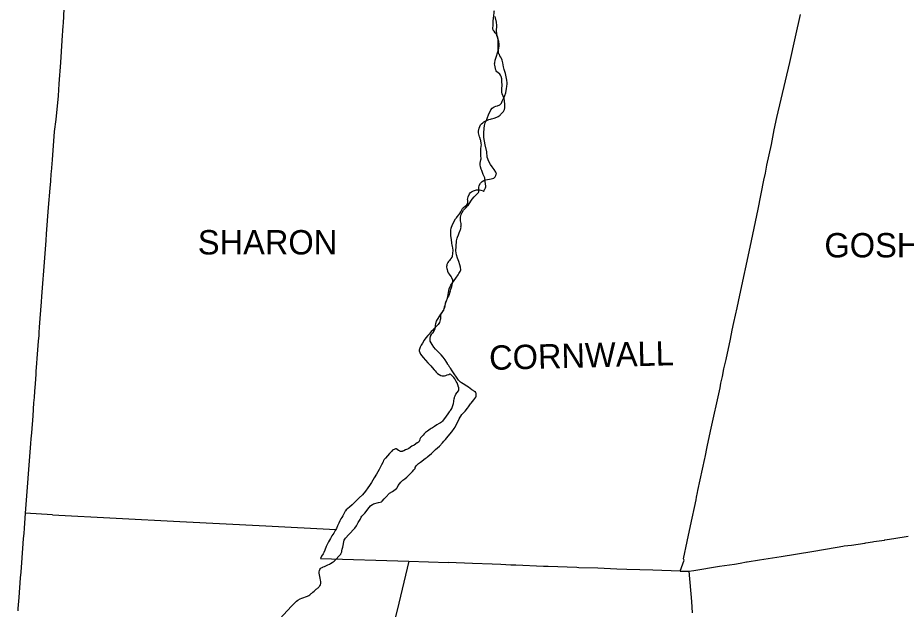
# Model space of a CAD drawing. Extents: x 0 to 2603, y -226 to 830.
# Drawn here: x 58.42 to 107.65, y 640.75 to 673.53 of the extents above; entities that cross this region are included whole.
import ezdxf

# ---------------------------------------------------------------- set-up
doc = ezdxf.new("R2010")
doc.units = 0
for name, color, linetype in [('CT_TSH_Map_Town_Limits', 7, 'Continuous'), ('CT_TSH_Map_Town_Text', 7, 'Continuous'), ('CT_TSH_Map_US_and_State_Routes', 7, 'Continuous')]:
    doc.layers.add(name, color=color, linetype=linetype)

msp = doc.modelspace()

# ---------------------------------------------------------------- linework, layer by layer
at = {"layer": 'CT_TSH_Map_Town_Limits'}
for points in [[(61.031, 675.236), (60.931, 673.222), (60.919, 673.075), (60.872, 672.278), (60.785, 671.041), (60.705, 669.873), (60.659, 669.204), (60.531, 667.883), (60.444, 667.228), (60.323, 665.65), (60.273, 664.984), (60.26, 664.878), (60.234, 664.477), (60.199, 664.083), (60.116, 663.02), (60.001, 661.559), (59.983, 661.187), (59.902, 660.217), (59.743, 658.078), (59.723, 657.778), (59.65, 656.871), (59.618, 656.382), (59.59, 656.089), (59.582, 655.911), (59.553, 655.613), (59.484, 654.647), (59.47, 654.38), (59.432, 653.916), (59.426, 653.757), (59.397, 653.509), (59.382, 653.246), (59.352, 652.835), (59.33, 652.478), (59.301, 652.195), (59.255, 651.46), (59.176, 650.527), (59.153, 650.196), (59.129, 649.932), (58.837, 646.072)], [(85.403, 668.545), (85.402, 668.697), (85.393, 668.942), (85.364, 669.049), (85.271, 669.317), (85.248, 669.411), (85.242, 669.486), (85.248, 669.583), (85.254, 669.79), (85.251, 670.005), (85.235, 670.148), (85.204, 670.276), (85.167, 670.355), (85.131, 670.4), (85.017, 670.499), (84.966, 670.538), (84.926, 670.588), (84.916, 670.618), (84.848, 670.904), (84.846, 670.97), (84.851, 671.033), (84.882, 671.179), (84.93, 671.337), (85.027, 671.636), (85.081, 671.839), (85.099, 671.972), (85.089, 672.094), (85.072, 672.184), (85.071, 672.212), (85.044, 672.318), (84.986, 672.528), (84.952, 672.783), (84.967, 673.091), (84.941, 673.29), (84.88, 673.593)], [(95.121, 642.851), (95.342, 643.466), (95.314, 643.536), (95.51, 644.512), (95.692, 645.37), (96.004, 646.816), (96.032, 646.954), (96.09, 647.22), (96.112, 647.327), (96.492, 649.109), (96.504, 649.174), (96.626, 649.752), (96.813, 650.615), (97.336, 653.016), (97.386, 653.287), (97.467, 653.654), (97.553, 654.065), (97.668, 654.59), (97.913, 655.716), (98.01, 656.213), (98.104, 656.639), (98.28, 657.458), (98.425, 658.157), (99, 660.816), (99.442, 662.918), (99.769, 664.522), (99.844, 664.916), (99.934, 665.357), (100.177, 666.51), (100.335, 667.321), (100.477, 668.008), (101.195, 671.043), (101.524, 672.472), (101.79, 673.71)], [(82.387, 660.139), (82.432, 660.184), (82.486, 660.263), (82.507, 660.312), (82.533, 660.465), (82.543, 660.652), (82.533, 660.765), (82.512, 660.872), (82.499, 660.91), (82.48, 661.054), (82.471, 661.08), (82.431, 661.353), (82.423, 661.451), (82.416, 661.51), (82.418, 661.536), (82.423, 661.759), (82.439, 661.872), (82.449, 661.924), (82.486, 662.019), (82.601, 662.247), (82.685, 662.383), (82.73, 662.445), (82.775, 662.497), (82.861, 662.606), (82.919, 662.676), (82.971, 662.774), (83.058, 662.954), (83.102, 663.001), (83.225, 663.107), (83.28, 663.141), (83.306, 663.162), (83.34, 663.209), (83.357, 663.259), (83.361, 663.305), (83.357, 663.413), (83.347, 663.458), (83.354, 663.53), (83.373, 663.603), (83.449, 663.776), (83.506, 663.842), (83.572, 663.889), (83.634, 663.922), (83.672, 663.94), (83.837, 663.988), (83.926, 663.998), (83.999, 663.988), (84.075, 663.971), (84.203, 663.929), (84.236, 663.918), (84.247, 663.919), (84.264, 663.944), (84.292, 664.002), (84.302, 664.035), (84.333, 664.102), (84.352, 664.154), (84.357, 664.197), (84.32, 664.446), (84.316, 664.525), (84.304, 664.596), (84.297, 664.662), (84.253, 664.769), (84.215, 664.851), (84.135, 665.069), (84.102, 665.141), (84.062, 665.271), (84.039, 665.387), (84.04, 665.462), (84.082, 665.656), (84.092, 665.714), (84.089, 665.9), (84.087, 666.269), (84.103, 666.407), (84.111, 666.478), (84.104, 666.569), (84.083, 666.719), (84.071, 666.768), (84.02, 666.887), (84.011, 666.933), (83.968, 667.081), (83.957, 667.156), (83.958, 667.24), (83.994, 667.402), (84.025, 667.494), (84.071, 667.598), (84.115, 667.658), (84.184, 667.715), (84.25, 667.759), (84.319, 667.792), (84.443, 667.853), (84.516, 667.887), (84.615, 667.915), (84.668, 667.934), (84.818, 667.973), (84.967, 668.019), (85.036, 668.048), (85.15, 668.139), (85.174, 668.163), (85.334, 668.34), (85.381, 668.413), (85.392, 668.442), (85.403, 668.545)], [(82.387, 660.139), (82.345, 660.069), (82.294, 660.014), (82.257, 659.958), (82.224, 659.893), (82.202, 659.847), (82.189, 659.797), (82.181, 659.751), (82.187, 659.7), (82.192, 659.642), (82.206, 659.573), (82.239, 659.492), (82.278, 659.393), (82.325, 659.322), (82.364, 659.272), (82.382, 659.262)], [(82.374, 658.356), (82.403, 658.426), (82.474, 658.642), (82.531, 658.889), (82.528, 658.978), (82.472, 659.107), (82.437, 659.19), (82.403, 659.242), (82.382, 659.262)], [(82.374, 658.356), (82.349, 658.262), (82.322, 658.192), (82.285, 658.105), (82.242, 658.02), (82.193, 657.908), (82.143, 657.798), (82.106, 657.693), (82.081, 657.584), (82.056, 657.491), (82.028, 657.39), (82.004, 657.323), (81.956, 657.255), (81.887, 657.143), (81.862, 657.075), (81.849, 657.049), (81.849, 656.983), (81.837, 656.851), (81.82, 656.781), (81.802, 656.712), (81.782, 656.639), (81.753, 656.576), (81.717, 656.531), (81.635, 656.449), (81.55, 656.366), (81.499, 656.303), (81.417, 656.213), (81.332, 656.134), (81.213, 655.991), (81.145, 655.923), (81.026, 655.782), (80.938, 655.661), (80.84, 655.503), (80.767, 655.375), (80.723, 655.271), (80.673, 655.164), (80.668, 655.108), (80.671, 655.061), (80.692, 654.973), (80.734, 654.888), (80.876, 654.7), (81.147, 654.406), (81.31, 654.236), (81.385, 654.154), (81.5, 654.016), (81.554, 653.953), (81.612, 653.884), (81.683, 653.82), (81.768, 653.763), (81.87, 653.711), (81.93, 653.691), (81.987, 653.68), (82.063, 653.681), (82.137, 653.706), (82.209, 653.733), (82.282, 653.758), (82.318, 653.755), (82.342, 653.774)], [(82.326, 651.687), (82.405, 651.762), (82.469, 651.882), (82.513, 651.99), (82.557, 652.148), (82.581, 652.271), (82.581, 652.301), (82.606, 652.409), (82.624, 652.469), (82.63, 652.501), (82.652, 652.573), (82.704, 652.672), (82.763, 652.756), (82.845, 652.845), (82.862, 652.89), (82.863, 652.96), (82.859, 653.012), (82.831, 653.109), (82.828, 653.127), (82.787, 653.246), (82.761, 653.3), (82.718, 653.377), (82.64, 653.51), (82.58, 653.593), (82.493, 653.69), (82.424, 653.754), (82.374, 653.774), (82.342, 653.774)], [(82.326, 651.687), (82.243, 651.575), (82.156, 651.454), (82.068, 651.315), (81.989, 651.219), (81.954, 651.17), (81.931, 651.145), (81.911, 651.123), (81.897, 651.112), (81.846, 651.08), (81.763, 651.035), (81.649, 650.963), (81.515, 650.881), (81.404, 650.809), (81.321, 650.759), (81.268, 650.73), (81.204, 650.681), (81.118, 650.614), (81.021, 650.54), (80.933, 650.461), (80.877, 650.4), (80.825, 650.343), (80.765, 650.273), (80.745, 650.252), (80.705, 650.174), (80.684, 650.107), (80.655, 650.051), (80.621, 650.016), (80.606, 650.005), (80.575, 649.978), (80.554, 649.966), (80.388, 649.848), (80.264, 649.78), (80.086, 649.666), (80.016, 649.623), (79.915, 649.579), (79.805, 649.529), (79.758, 649.508), (79.738, 649.507), (79.713, 649.498), (79.673, 649.491), (79.65, 649.491), (79.629, 649.495), (79.6, 649.505), (79.568, 649.52), (79.512, 649.55), (79.453, 649.609), (79.438, 649.621), (79.424, 649.629), (79.402, 649.634), (79.383, 649.637), (79.356, 649.634), (79.322, 649.624), (79.272, 649.605), (79.221, 649.576), (79.19, 649.556), (79.142, 649.513), (79.011, 649.379), (78.792, 649.13), (78.731, 649.055), (78.697, 649.007), (78.683, 648.99), (78.66, 648.927), (78.57, 648.745), (78.442, 648.501), (78.291, 648.239), (78.167, 648.029), (78.026, 647.768), (77.92, 647.605), (77.824, 647.484), (77.682, 647.297), (77.517, 647.09), (77.341, 646.916), (77.145, 646.715), (76.949, 646.53), (76.805, 646.41), (76.712, 646.324), (76.628, 646.254), (76.587, 646.206), (76.562, 646.175), (76.503, 646.078), (76.433, 645.928), (76.375, 645.831), (76.332, 645.75), (76.272, 645.655), (76.208, 645.511), (76.136, 645.367), (76.075, 645.225), (76.042, 645.173)], [(58.837, 646.072), (58.769, 645.234), (58.756, 644.943), (58.728, 644.665), (58.711, 644.39), (58.589, 642.806), (58.559, 642.488), (58.477, 641.393), (58.436, 640.783), (58.423, 640.667)], [(60.341, 645.972), (58.837, 646.072)], [(60.341, 645.972), (67.41, 645.603), (72.165, 645.364), (76.042, 645.173)], [(76.042, 645.173), (76.005, 645.117), (75.93, 644.97), (75.833, 644.82), (75.746, 644.668), (75.641, 644.484), (75.567, 644.337), (75.513, 644.226), (75.431, 644.026), (75.38, 643.893), (75.352, 643.816), (75.258, 643.681), (75.193, 643.555), (80.1, 643.411)], [(95.609, 642.852), (95.882, 642.894), (97.308, 643.128), (98.127, 643.255), (98.457, 643.31), (98.793, 643.367), (98.846, 643.373), (99.523, 643.488), (100.712, 643.675), (102.416, 643.953), (103.83, 644.191), (104.146, 644.238), (104.22, 644.254), (104.611, 644.307), (105.36, 644.411), (105.409, 644.427), (105.785, 644.479), (105.859, 644.496), (106.447, 644.585), (106.467, 644.593), (106.726, 644.625), (107.53, 644.765), (107.764, 644.793)], [(80.1, 643.411), (79.534, 641.088), (78.955, 638.71), (77.491, 637.157), (77.606, 636.187)], [(80.1, 643.411), (82.266, 643.331)], [(95.121, 642.851), (93.603, 642.911), (92.167, 642.96), (91.611, 642.977), (90.56, 643.019), (89.515, 643.051), (89.391, 643.06), (87.807, 643.12), (87.556, 643.124), (86.019, 643.188), (85.738, 643.197), (85.183, 643.223), (84.71, 643.238), (83.611, 643.28), (82.266, 643.331)], [(95.121, 642.851), (95.609, 642.852)], [(95.609, 642.852), (95.751, 641.169), (95.796, 640.551)]]:
    msp.add_lwpolyline(points, dxfattribs=at)
at = {"layer": 'CT_TSH_Map_US_and_State_Routes'}
for points in [[(84.759, 673.118), (84.759, 673.199), (84.763, 673.334), (84.775, 673.513), (84.81, 673.794), (84.826, 673.878), (84.837, 673.94)], [(84.877, 672.696), (84.819, 672.778), (84.772, 672.847), (84.753, 672.926), (84.759, 673.118)], [(84.976, 672.548), (84.943, 672.616), (84.877, 672.696)], [(85.014, 672.449), (84.976, 672.548)], [(85.044, 671.877), (85.032, 672.261), (85.032, 672.343), (85.014, 672.449)], [(85.055, 671.604), (85.044, 671.877)], [(85.219, 671.273), (85.18, 671.35), (85.142, 671.416), (85.107, 671.486), (85.081, 671.525), (85.055, 671.604)], [(85.256, 671.184), (85.219, 671.273)], [(85.408, 669.221), (85.457, 669.372), (85.489, 669.496), (85.503, 669.596), (85.526, 669.733), (85.537, 669.856), (85.537, 669.92), (85.517, 670.075), (85.488, 670.255), (85.438, 670.435), (85.381, 670.667), (85.357, 670.735), (85.335, 670.818), (85.304, 671.024), (85.256, 671.184)], [(84.702, 665.267), (84.608, 665.397), (84.517, 665.564), (84.437, 665.798), (84.415, 666.098), (84.317, 666.493), (84.239, 666.897), (84.246, 667.145), (84.27, 667.39), (84.29, 667.56), (84.325, 667.705), (84.406, 667.89), (84.446, 668), (84.501, 668.156), (84.637, 668.427), (84.715, 668.525), (84.813, 668.586), (84.914, 668.627), (85.013, 668.653), (85.134, 668.708), (85.218, 668.803), (85.267, 668.898), (85.339, 669.047), (85.374, 669.126), (85.386, 669.159)], [(85.386, 669.159), (85.408, 669.221)], [(84.811, 665.125), (84.702, 665.267)], [(84.918, 664.969), (84.811, 665.125)], [(83.972, 663.918), (83.963, 664.057), (83.97, 664.128), (83.996, 664.229), (84.063, 664.358), (84.158, 664.455), (84.245, 664.509), (84.326, 664.542), (84.442, 664.567), (84.556, 664.579), (84.662, 664.596), (84.794, 664.644), (84.875, 664.71), (84.917, 664.781), (84.935, 664.856), (84.94, 664.88), (84.917, 664.969)], [(83.126, 662.862), (83.262, 663.016), (83.337, 663.098), (83.376, 663.131), (83.524, 663.364), (83.592, 663.476), (83.704, 663.604), (83.808, 663.7), (83.885, 663.771), (83.947, 663.841), (83.971, 663.887), (83.972, 663.918)], [(82.984, 662.121), (82.977, 662.193), (82.962, 662.272), (82.951, 662.359), (82.953, 662.487), (82.986, 662.617), (83.039, 662.736)], [(83.039, 662.736), (83.126, 662.862)], [(82.794, 661.361), (82.84, 661.492), (82.881, 661.605), (82.908, 661.704), (82.931, 661.743), (82.959, 661.788), (82.972, 661.829), (82.981, 661.861), (82.984, 661.925), (82.981, 661.97), (82.984, 662.023), (82.984, 662.121)], [(82.714, 660.938), (82.729, 661.068), (82.736, 661.167), (82.751, 661.247), (82.775, 661.32), (82.794, 661.361)], [(82.863, 659.35), (82.943, 659.466), (82.971, 659.565), (82.955, 659.7), (82.908, 659.83), (82.856, 660.012), (82.789, 660.206), (82.726, 660.396), (82.69, 660.614), (82.705, 660.858), (82.714, 660.938)], [(82.065, 657.437), (82.097, 657.555), (82.118, 657.693), (82.173, 657.836), (82.229, 657.988), (82.256, 658.103), (82.272, 658.179), (82.282, 658.306), (82.318, 658.512), (82.417, 658.712), (82.686, 659.088), (82.817, 659.286), (82.863, 659.35)], [(81.565, 656.366), (81.568, 656.47), (81.58, 656.588), (81.619, 656.717), (81.867, 657.111), (81.934, 657.194), (81.996, 657.287), (82.065, 657.437)], [(81.272, 655.748), (81.296, 655.883), (81.339, 655.974), (81.391, 656.046), (81.433, 656.092), (81.496, 656.171), (81.548, 656.28), (81.565, 656.366)], [(81.787, 654.946), (81.741, 654.988), (81.696, 655.034), (81.654, 655.077), (81.572, 655.169), (81.481, 655.279), (81.39, 655.415), (81.32, 655.518), (81.28, 655.612), (81.269, 655.677), (81.272, 655.748)], [(82.204, 654.415), (82.101, 654.571), (81.986, 654.715), (81.876, 654.846), (81.811, 654.919), (81.787, 654.946)], [(82.383, 654.13), (82.365, 654.155), (82.349, 654.178), (82.334, 654.2), (82.319, 654.219), (82.31, 654.23), (82.28, 654.269), (82.267, 654.286), (82.253, 654.311), (82.242, 654.333), (82.23, 654.36), (82.204, 654.415)], [(82.852, 653.453), (82.499, 653.966), (82.398, 654.11), (82.383, 654.13)], [(82.905, 653.386), (82.852, 653.453)], [(82.955, 653.336), (82.905, 653.386)], [(83.3, 653.116), (83.098, 653.232), (83.007, 653.292), (82.955, 653.336)], [(83.401, 653.049), (83.3, 653.116)], [(83.493, 652.983), (83.401, 653.049)], [(83.584, 652.917), (83.493, 652.983)], [(83.78, 652.794), (83.776, 652.795), (83.752, 652.804), (83.704, 652.83), (83.678, 652.85), (83.652, 652.869), (83.584, 652.917)], [(83.819, 652.577), (83.824, 652.611), (83.825, 652.621), (83.825, 652.63), (83.825, 652.652), (83.822, 652.679), (83.816, 652.707), (83.807, 652.735), (83.795, 652.767), (83.78, 652.794)], [(83.542, 652.169), (83.697, 652.358), (83.808, 652.501)], [(83.808, 652.501), (83.817, 652.562), (83.819, 652.577)], [(83.204, 651.734), (83.339, 651.897), (83.398, 651.966), (83.478, 652.084), (83.503, 652.125), (83.542, 652.169)], [(82.035, 650.072), (82.121, 650.165), (82.273, 650.335), (82.466, 650.589), (82.597, 650.762), (82.65, 650.846), (82.887, 651.31), (82.931, 651.393), (82.973, 651.449), (83.034, 651.537), (83.069, 651.579), (83.204, 651.734)], [(81.781, 649.789), (81.949, 649.976), (82.035, 650.072)], [(81.152, 649.222), (81.347, 649.389)], [(81.347, 649.389), (81.441, 649.477)], [(81.441, 649.477), (81.575, 649.601)], [(81.575, 649.601), (81.781, 649.789)], [(80.45, 648.596), (80.5, 648.693), (80.534, 648.731), (80.635, 648.824), (80.74, 648.904)], [(80.74, 648.904), (80.989, 649.097)], [(80.989, 649.097), (81.098, 649.181)], [(81.098, 649.181), (81.152, 649.222)], [(80.201, 648.282), (80.296, 648.385), (80.367, 648.472)], [(80.367, 648.472), (80.435, 648.555)], [(80.435, 648.555), (80.45, 648.596)], [(79.655, 647.785), (79.762, 647.895), (79.866, 647.976), (79.973, 648.068), (80.201, 648.282)], [(78.721, 646.86), (78.817, 646.968), (79.028, 647.177), (79.178, 647.282), (79.407, 647.443), (79.443, 647.478), (79.506, 647.603), (79.573, 647.703), (79.655, 647.785)], [(78.038, 646.535), (78.076, 646.562), (78.125, 646.588), (78.419, 646.666), (78.509, 646.684), (78.574, 646.704), (78.62, 646.73), (78.721, 646.86)], [(77.386, 645.73), (77.454, 645.845), (77.49, 645.913), (77.66, 646.082), (77.897, 646.378), (77.975, 646.474), (78.038, 646.535)], [(77.102, 645.236), (77.195, 645.377), (77.293, 645.561), (77.386, 645.73)], [(76.428, 644.195), (76.507, 644.569), (76.584, 644.681), (76.767, 644.888), (77.102, 645.236)], [(76.289, 643.759), (76.316, 643.792), (76.331, 643.817), (76.347, 643.848), (76.362, 643.887), (76.372, 643.93), (76.386, 643.989), (76.402, 644.072), (76.416, 644.138), (76.428, 644.195)], [(75.845, 643.331), (75.9, 643.372), (75.945, 643.407), (75.991, 643.447), (76.051, 643.506), (76.24, 643.707)], [(76.24, 643.707), (76.251, 643.719)], [(76.251, 643.719), (76.289, 643.759)], [(74.71, 641.637), (74.769, 641.689), (74.846, 641.756), (74.889, 641.794), (74.924, 641.825), (74.958, 641.852), (74.988, 641.879), (75.026, 641.912), (75.061, 641.939), (75.098, 641.972), (75.129, 642.009), (75.159, 642.054), (75.188, 642.106), (75.208, 642.173), (75.216, 642.232), (75.217, 642.287), (75.206, 642.354), (75.173, 642.464), (75.151, 642.57), (75.137, 642.655), (75.131, 642.739), (75.131, 642.82), (75.141, 642.887), (75.167, 642.953), (75.206, 642.999), (75.242, 643.038), (75.287, 643.065)], [(75.287, 643.065), (75.317, 643.083)], [(75.317, 643.083), (75.35, 643.094)], [(75.35, 643.094), (75.417, 643.125)], [(75.417, 643.125), (75.604, 643.21), (75.692, 643.248), (75.742, 643.275), (75.845, 643.331)], [(74.064, 641.329), (74.155, 641.363), (74.267, 641.399), (74.373, 641.434), (74.428, 641.452), (74.472, 641.471), (74.547, 641.51), (74.604, 641.55), (74.686, 641.618)], [(74.686, 641.618), (74.71, 641.637)], [(71.406, 638.555), (73.584, 640.927), (73.638, 640.982), (73.741, 641.068), (73.806, 641.133), (73.875, 641.199), (73.94, 641.25), (74.064, 641.329)]]:
    msp.add_lwpolyline(points, dxfattribs=at)

# ---------------------------------------------------------------- texts
at = {"layer": 'CT_TSH_Map_Town_Text'}
for s, p in [('SHARON', (68.401, 660.412)), ('GOSHEN', (103.116, 660.248))]:
    msp.add_text(s, height=1.35, dxfattribs=at).set_placement(p)
msp.add_text('CORNWALL', height=1.35, rotation=1.4817, dxfattribs=at).set_placement((84.555, 654.008))

doc.saveas('drawing.dxf')
